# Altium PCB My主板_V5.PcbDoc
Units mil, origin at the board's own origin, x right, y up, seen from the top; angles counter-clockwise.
Board outline 4125 x 2480.2 mil, 2 copper layers (Top Layer, Bottom Layer); 56 components, 56 nets, 301 pads, 42 vias.
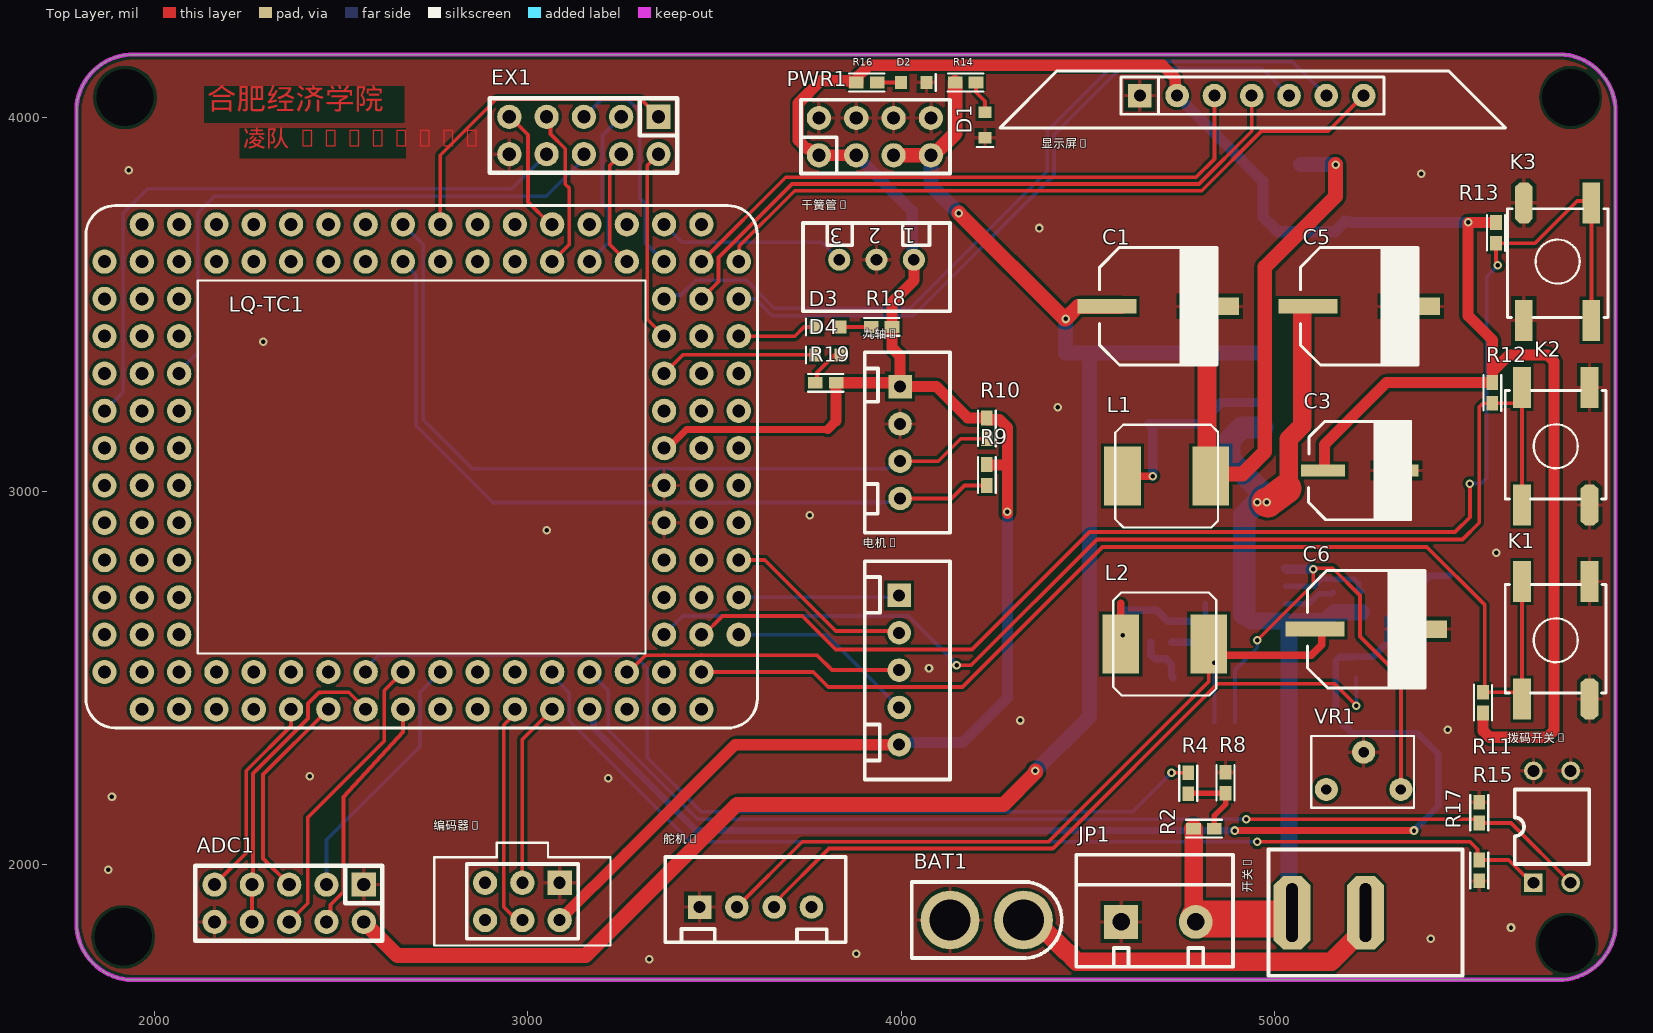
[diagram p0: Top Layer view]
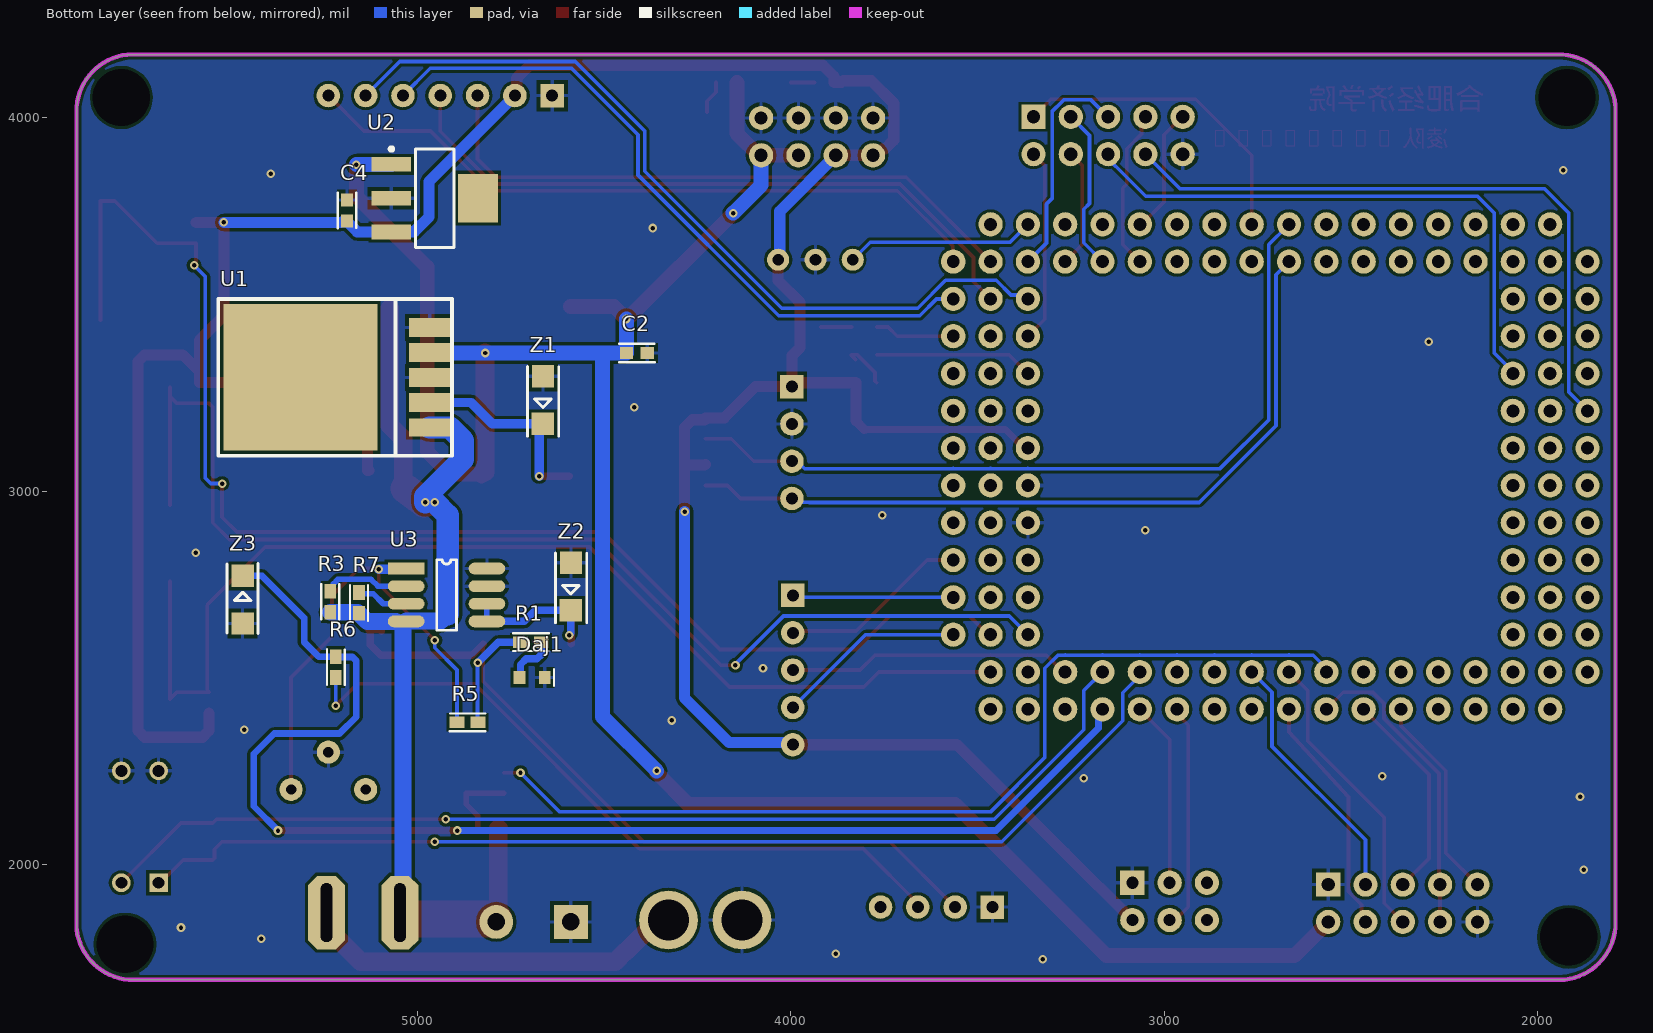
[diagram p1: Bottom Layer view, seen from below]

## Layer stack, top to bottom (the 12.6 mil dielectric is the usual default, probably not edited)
Top Solder: solder mask 0.4, Solder Resist, Dk 3.5
Top Layer: signal copper 1.4
Dielectric 1: dielectric 12.6, FR-4, Dk 4.8
Bottom Layer: signal copper 1.4
Bottom Solder: solder mask 0.4, Solder Resist, Dk 3.5

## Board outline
1790,1830 ccw(c1943.01,1842.73) 1925.4,1690.2 1925.4,1689.8 5775,1689.8 5775,1690 ccw(c5762.27,1843.01) 5914.8,1825.4 5915,1825.4 5915,4030 ccw(c5761.99,4017.27) 5779.6,4169.8 5779.6,4170 1930,4170 ccw(c1942.73,4016.99) 1790.2,4034.6 1790,4034.6

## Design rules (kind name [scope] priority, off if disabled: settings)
Clearance [All] p1: gap=8 ignorepadtopadclearanceinfootprint=FALSE
PolygonConnect [All] p1: thpad.connectstyle=Relief thpad.reliefconductorwidth=10 thpad.reliefentries=4 thpad.polygonreliefangle="90 Angle" thpad.airgapwidth=10 smdpad.connectstyle=Relief smdpad.reliefconductorwidth=10 smdpad.reliefentries=4 smdpad.polygonreliefangle="90 Angle" smdpad.airgapwidth=10 via.connectstyle=Direct via.reliefconductorwidth=10 via.reliefentries=4 via.polygonreliefangle="90 Angle" via.airgapwidth=10
RoutingVias [All] p1: holewidth=12 width=25 viastyle="Through Hole" minholewidth=12 minwidth=22 maxholewidth=12 maxwidth=50
SolderMaskExpansion [All] p1: expansion=4 istentingtop=FALSE
Width 12V [InNetClass('12V')] p1: maxlimit=100 minlimit=10 preferedwidth=50
Width 5V [InNetClass('5V')] p2: maxlimit=100 minlimit=10 preferedwidth=40
Width 3.3V [InNetClass('3.3V')] p3: maxlimit=100 minlimit=10 preferedwidth=30
Width [All] p4: maxlimit=100 minlimit=10 preferedwidth=10
30 further rules are at their usual default settings.

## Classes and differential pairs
net class 3.3V: 3.3V
net class 5V: 5V
net class 12V: BAT12V VCC12V

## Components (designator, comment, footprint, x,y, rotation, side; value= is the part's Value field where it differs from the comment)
ADC1 "双排针2*5 2.5mm" LQ_IDC5X2 2560,1945 r180 top
BAT1 "XT30UPB-M公头" LQ_XT30UPB-F 4230,1850 r180 top
C1 "470uf/16V  8*10" LQ_C8X10 4690,3495 r180 top
C2 "104nF" LQ_C0603 4441,3370 r180 bottom value=104
C3 "470uf/10V  6.3*7.7" LQ_C6d3X7d7 5230,3055 r180 top
C4 "104nF" LQ_C0603 5190,3780 r270 bottom value=104
C5 "220uf/16V  8*10" LQ_C8X10 5228.43,3495 r180 top
C6 "470uf/16V  8*10" LQ_C8X10 5247.2,2630 r180 top
D1 "LED红" LQ_LED0603R 4225,4015 r270 top
D2 "LED红" LQ_LED0603R 4000,4095 r0 top
D3 "LED红" LQ_LED0603R 3838,3440 r180 top
D4 "LED红" LQ_LED0603R 3838,3365 r180 top
Daj1 "LED红" LQ_LED0603R 4728,2500 r180 bottom
EX1 "单排针2*5-2.54mm" LQ_IDC5X2 3350,4003 r180 top
JP1 "HDR-1X2" KF301-5.0-2P 4790,1845 r0 top
K1 "微动开关6*6*6" LQ_BT4SMT 5755,2600 r180 top
K2 "微动开关6*6*6" LQ_BT4SMT 5755,3120 r180 top
K3 "微动开关6*6*6" LQ_BT4SMT 5760,3615 r0 top
L1 "33uH" LQ_L7X7 4593.78,3040 r0 top
L2 "33uH" LQ_L7X7 4588.78,2590 r0 top
LQ-TC1 "LQ-TC264-SYSVC" LQ-TC264-SYSVC-S 1965,2415 r0 top
PWR1 "双排针4X2-2.54" LQ_IDC4X2 3780,3900 r90 top
R1 "3K3" LQ_R0603 4669,2595 r0 bottom
R2 "4.7K" LQ_R0603 4784,2095 r0 top
R3 "1K" LQ_R0603 5235,2731 r270 bottom
R4 "2K" LQ_R0603 4770,2245 r270 top
R5 "1K" LQ_R0603 4895,2380 r180 bottom
R6 "2K" LQ_R0603 5220,2556 r270 bottom
R7 "2.7K" LQ_R0603 5158,2672 r90 bottom
R8 "1K" LQ_R0603 4870,2190 r90 top
R9 "2.2K" LQ_R0603 4230,3071 r270 top
R10 "2.2K" LQ_R0603 4230,3140 r90 top
R11 "1K" LQ_R0603 5560,2461 r270 top
R12 "1K" LQ_R0603 5585,3235 r90 top
R13 "1K" LQ_R0603 5595,3664 r90 top
R14 "1K" LQ_R0603 4145,4095 r0 top
R15 "2.2K" LQ_R0603 5550,2110 r90 top
R16 "1K" LQ_R0603 3880,4095 r0 top
R17 "2.2K" LQ_R0603 5550,2011 r270 top
R18 "1K" LQ_R0603 3976,3440 r180 top
R19 "1K" LQ_R0603 3826,3290 r180 top
U1 "LM2596CS-5.0V" LQ_TO-263-5 4968.54,3170.35 r90 bottom
U2 "LM39100 3.3V" SOT223_M 4955,3785 r180 bottom
U3 "AS1015" SOP8 5031.54,2792.24 r180 bottom
VR1 "2k" lq_3266 5140,2200 r0 top
Z1 "1N5824" LQ_1206D 4664.61,3307.56 r270 bottom
Z2 "1N5824" LQ_1206D 4589.61,2807.56 r270 bottom
Z3 "ZMM3V3" LQ_1206D 5470,2645 r90 bottom
九轴1 "插针1*4" LQ_XH254-4P 4017.05,3280 r270 top
干簧管1 "XH254-3P" LQ_XH254-3P 4034.37,3620 r180 top
开关1 "KCD1-101 117S" "LQ_KCD1-101 117S" 5245,1870 r0 top
拨码开关1 "SW-DIP2" DIP4 5695,1950 r90 top
显示屏1 "单排座1*7-2.54" LQ-TFT-180V33 4940,4060 r0 top
电机1 "XH254-4P" LQ_XH254-5P 3995,2520 r270 top
编码器1 "双排针2*3 2.54mm" LQ_ENCODER 3085,1950 r180 top
舵机1 "插针1*4-2.54" LQ_XH254-4P 3460,1904.68 r0 top

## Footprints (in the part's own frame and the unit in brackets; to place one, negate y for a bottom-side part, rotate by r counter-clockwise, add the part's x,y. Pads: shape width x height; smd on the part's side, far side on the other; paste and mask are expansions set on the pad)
DIP4 [mil]
  rect 50x50 hole 32: 1(0,0)
  round 50 hole 32: 2(0,-100) 3(300,-100) 4(300,0)
  silkscreen extent 50,-150 250,50, body extent -45,-170 345,70, height 276
KF301-5.0-2P [mm]
  rect 2.3x2.3 hole 1.2: 1(-5.08,0)
  round 2.3 hole 1.2: 2(0,0)
  silkscreen extent -8.13,-3.05 2.54,4.57, body extent -7.95,-3 2.55,4.6, height 10.05
LQ-TC264-SYSVC-S [mm] "单片机核心板封装库"
  round 1.65 hole 0.88: 1(5.08,0) 2(5.08,2.54) 3(7.62,0) 4(7.62,2.54) 5(10.16,0) 6(10.16,2.54) 7(12.7,0) 8(12.7,2.54) 9(15.24,0) 10(15.24,2.54) 11(17.78,0) 12(17.78,2.54) 13(20.32,0) 14(20.32,2.54) 15(22.86,0) 16(22.86,2.54) 17(25.4,0) 18(25.4,2.54) 19(27.94,0) 20(27.94,2.54) 21(30.48,0) 22(30.48,2.54) 23(33.02,0) 24(33.02,2.54) 25(35.56,0) 26(35.56,2.54) 27(38.1,0) 28(38.1,2.54) 30(38.1,5.08) 31(35.56,5.08) 33(38.1,7.62) 34(35.56,7.62) 36(38.1,10.16) 37(35.56,10.16) 39(38.1,12.7) 40(35.56,12.7) 42(38.1,15.24) 43(35.56,15.24) 45(38.1,17.78) 46(35.56,17.78) 48(38.1,20.32) 49(35.56,20.32) 51(38.1,22.86) 52(35.56,22.86) 54(38.1,25.4) 55(35.56,25.4) 57(38.1,27.94) 58(35.56,27.94) 60(38.1,30.48) 61(35.56,30.48) 62(38.1,33.02) 63(35.56,33.02) 64(33.02,33.02) 65(33.02,30.48) 66(30.48,33.02) 67(30.48,30.48) 68(27.94,33.02) 69(27.94,30.48) 70(25.4,33.02) 71(25.4,30.48) 72(22.86,33.02) 73(22.86,30.48) 74(20.32,33.02) 75(20.32,30.48) 76(17.78,33.02) 77(17.78,30.48) 78(15.24,33.02) 79(15.24,30.48) 80(12.7,33.02) 81(12.7,30.48) 82(10.16,33.02) 83(10.16,30.48) 84(7.62,33.02) 85(7.62,30.48) 86(5.08,33.02) 87(5.08,30.48) 88(2.54,33.02) 89(0,33.02) 90(2.54,30.48) 91(0,30.48) 93(2.54,27.94) 94(0,27.94) 96(2.54,25.4) 97(0,25.4) 99(2.54,22.86) 100(0,22.86) 102(2.54,20.32) 103(0,20.32) 105(2.54,17.78) 106(0,17.78) 108(2.54,15.24) 109(0,15.24) 111(2.54,12.7) 112(0,12.7) 114(2.54,10.16) 115(0,10.16) 117(2.54,7.62) 118(0,7.62) 120(2.54,5.08) 121(0,5.08) 123(2.54,2.54) 124(0,2.54) 126(2.54,0) 127(0,0)
  round 1.65 hole 0.88 mask+0.102: 29(40.64,5.08) 32(40.64,7.62) 35(40.64,10.16) 38(40.64,12.7) 41(40.64,15.24) 44(40.64,17.78) 47(40.64,20.32) 50(40.64,22.86) 53(40.64,25.4) 56(40.64,27.94) 59(40.64,30.48) 92(-2.54,30.48) 95(-2.54,27.94) 98(-2.54,25.4) 101(-2.54,22.86) 104(-2.54,20.32) 107(-2.54,17.78) 110(-2.54,15.24) 113(-2.54,12.7) 116(-2.54,10.16) 119(-2.54,7.62) 122(-2.54,5.08) 125(-2.54,2.54)
  silkscreen extent -3.81,-1.27 41.91,34.29
LQ-TFT-180V33 [mm]
  rect 1.6x1.6 hole 0.82: 1(-7.62,0)
  round 1.6 hole 0.82: 2(-5.08,0) 3(-2.54,0) 4(0,0) 5(2.54,0) 6(5.08,0) 7(7.62,0)
  silkscreen extent -17.13,-2.19 17.27,1.69
LQ_1206D [mil]
  rect 60x60 smd: 1(0,0) 2(127.56,-0.39)
  silkscreen extent -27,-41 161,42, body extent -4,-30 133,29, height 61
lq_3266 [mil]
  round 62 hole 28: 1(0,0) 2(100,100) 3(200,0)
  silkscreen extent -40,-49 235,143
LQ_BT4SMT [mm]
  oct 1.2x2.8 smd: 1(-2.3,4)
  rect 1.2x2.8 smd: 1(-2.3,-4) 2(2.3,4) 2(2.3,-4)
  silkscreen extent -3.42,-3.8 3.44,3.6, body extent -3,-5.08 3,4.92, height 4.54
LQ_C6d3X7d7 [mm]
  rect 3x0.8 smd: 1(2.5,0) 2(-2.5,0)
  silkscreen extent -3.49,-3.37 3.49,3.35, body extent -3.5,-3.3 3.5,3.3, height 7.7
LQ_C8X10 [mm]
  rect 4x1 smd: 1(3.5,0)
  rect 4x1.2 smd: 2(-3.5,0)
  silkscreen extent -4,-4 4,4, body extent -4.95,-4.15 4.95,4.15, height 10.2
LQ_C0603 [mm]
  rect 0.9x0.8 smd: 1(0,0) 2(1.422,0)
  silkscreen extent -0.5,-0.64 1.92,0.64, body extent -0.08,-0.4 1.52,0.4, height 0.3
LQ_ENCODER [mm]
  rect 1.65x1.65 hole 0.82: 1(0,0)
  round 1.65 hole 0.82: 2(0,2.54) 3(2.54,0) 4(2.54,2.54) 5(5.08,0) 6(5.08,2.54)
  silkscreen extent -3.46,-2.73 8.54,4.27, body extent -1.31,-1.31 6.31,3.77, height 8.5
LQ_IDC4X2 [mm]
  round 1.65 hole 0.9: 1(0,0) 2(2.54,0) 3(0,-2.54) 4(2.54,-2.54) 5(0,-5.08) 6(2.54,-5.08) 7(0,-7.62) 8(2.54,-7.62)
  silkscreen extent -1.24,-8.92 3.78,1.22, body extent -1.17,-9.01 3.83,1.4, height 8.5
LQ_IDC5X2 [mm]
  rect 1.65x1.65 hole 0.9: 1(0,0)
  round 1.65 hole 0.9: 2(0,2.54) 3(2.54,0) 4(2.54,2.54) 5(5.08,0) 6(5.08,2.54) 7(7.62,0) 8(7.62,2.54) 9(10.16,0) 10(10.16,2.54)
  silkscreen extent -1.27,-1.27 11.48,3.81, body extent -1.25,-1.26 11.45,3.82, height 8.5
"LQ_KCD1-101 117S" [mm]
  oct 2.5x5 hole 0.8 slot 4 at 90 deg: 1(0,0) 2(-5,0)
  silkscreen extent -6.61,-4.3 6.6,4.3
LQ_L7X7 [mm]
  rect 2.5x4 smd: 1(0,0) 2(6,0)
  silkscreen extent -0.5,-3.5 6.5,3.5
LQ_LED0603R [mm]
  rect 0.8x0.9 smd: 1(0,0) 2(1.727,0)
  silkscreen extent 2.36,-0.56 2.36,0.58, body extent 0.02,-0.45 1.72,0.45, height 0.9
LQ_R0603 [mm]
  rect 1x0.8 smd: 1(0,0) 2(1.422,0)
  silkscreen extent -0.5,-0.61 1.92,0.61, body extent -0.08,-0.4 1.52,0.4, height 0.48
LQ_TO-263-5 [mil]
  rect 393.7x413.39 smd: 0(134.65,346.46)
  rect 48x110 smd: 1(0,0)
  rect 50x110 smd: 2(67,0) 3(134,0) 4(201,0) 5(268,0)
  silkscreen extent -76,-60 344,567, body extent -65,-16 335,536, height 180
LQ_XH254-3P [mm]
  round 1.5 hole 0.8: 1(0,0) 2(2.54,0) 3(5.08,0)
  silkscreen extent -2.46,-2.5 7.54,3.5, body extent -2.43,-2.37 7.57,3.33, height 7
LQ_XH254-4P [mm]
  rect 1.6x1.6 hole 0.82: 1(0,-0.5)
  round 1.6 hole 0.82: 2(2.54,-0.5) 3(5.08,-0.5) 4(7.62,-0.5)
  silkscreen extent -2.33,-2.9 9.96,2.9, body extent -2.45,-2.81 10.05,2.89, height 7
LQ_XH254-5P [mm]
  rect 1.6x1.6 hole 0.82: 1(-5.08,0)
  round 1.6 hole 0.82: 2(-2.54,0) 3(0,0) 4(2.54,0) 5(5.08,0)
  silkscreen extent -7.42,-2.34 7.45,3.46, body extent -7.52,-2.31 7.48,3.39, height 7
LQ_XT30UPB-F [mm]
  round 4 hole 2.8: 1(2.5,0) 2(-2.5,0)
  silkscreen extent -5.1,-2.59 5.11,2.6
SOP8 [mm]
  rect 2.5x0.8 smd: 1(0,0)
  oval 2.5x0.8 smd: 2(0,-1.2) 3(0,-2.4) 4(0,-3.6) 5(5.5,-3.6) 6(5.5,-2.4) 7(5.5,-1.2) 8(5.5,0)
  silkscreen extent 2.08,-4.2 3.41,0.6
SOT223_M [mm] "SOT223, 4-Leads, Body 6.5x3.5mm, Pitch 2.3mm, Lead Span 7mm, IPC Low Density"
  rect 2.7x1 smd: 1(-2.95,2.3) 2(-2.95,0) 3(-2.95,-2.3)
  rect 2.7x3.3 smd: 4(2.95,0)
  silkscreen extent -3.08,-3.35 1.3,3.47, body extent -1.85,-3.35 1.85,3.35, height 1.7

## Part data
ADC1: library part CON10, "Connector"
BAT1: library part LQ_PIN2, "Jumper"
C1 C3 C5 C6: library part "CAPACITOR POL", "Capacitor"
C2 C4: library part Cap, "Capacitor"
D1 D2 D3 D4: library part LED
Daj1: library part LQ_LED
EX1: library part "HEADER 5X2"
JP1: library part "Header 2_1", "2P接插件"
K1 K2 K3: library part 微动开关
L1 L2: library part INDUCTOR
PWR1: library part "HEADER 4X2"
R1 R2 R3 R4 R5 R6 R7 R8 R9 R10 R11 R12 R13 R14 R15 R16 R17 R18 R19: library part RES2
U1: library part LM2575T
U2: library part VOLTREG
VR1: library part "RESISTOR TAPPED"
Z1 Z2 Z3: library part LQ_D, "Schottky Diode"
九轴1 舵机1: library part CON4, "Connector"
干簧管1: library part "HEADER 3"
开关1: library part LQ_SWMTS102, "LQ_SWMTS102"
显示屏1: library part LQ_OLED128X64
电机1: library part "Header 5", "Header, 5-Pin"
编码器1: library part "Header 3X2", "Header, 3-Pin, Dual row"

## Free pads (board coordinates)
  round 60 hole 153.54: 2(1915,1805) 2(1920,4055) 2(5785,1785) 2(5795,4055)

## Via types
v1: diameter 23, hole 12, Top Layer to Bottom Layer, tented both sides, 42 vias

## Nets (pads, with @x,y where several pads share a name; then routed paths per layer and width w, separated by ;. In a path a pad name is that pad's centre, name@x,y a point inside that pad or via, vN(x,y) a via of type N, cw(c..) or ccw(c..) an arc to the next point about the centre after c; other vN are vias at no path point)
3.3V: C3.1 C4.2 LQ-TC1.46 PWR1.1 PWR1.3 R9.1 R10.2 R11.2 R12.2 R13.2 R16.1 R18.1 R19.1 U2.3 九轴1.1 干簧管1.1 显示屏1.2 电机1.5 编码器1.2 | length 8951
  Top Layer w18: LQ-TC1.46 3375,3115 3425,3165 3803.43,3165
  Top Layer w25: 3803.43,3165 3826,3187.57
  Top Layer w30: 编码器1.2 3265,2030 3555,2320 电机1.5 ; PWR1.1 3770.54,3900 3753.25,3917.29 3747.71,3917.29 3724.52,3940.48 3724.52,4039.52 3785,4100 3860.78,4100 3865.03,4095.75 3875.32,4095.75 3876.06,4095 3883.94,4095 3884.68,4095.75 3884.68,4105 3884.68,4111.65 3914.13,4141.09 4701.33,4141.09 4735,4107.43 4735,4065 显示屏1.2 ; PWR1.1@3801.54,3900 PWR1.3 ; 3826,3187.57 R19.1 3987.36,3290 九轴1.1 3997.36,3362.64 3976,3384 R18.1 3976,3506 4034.37,3564.37 干簧管1.1 ; 九轴1.1@4020,3280 4095,3280 4179,3196 R10.2 4230,3192.06 4230.75,3191.32 4263.69,3191.32 4285,3170 v1(4285,2945) v1@4285,2940.07 ; R9.1 4230,3070.75 4230.75,3070 4270.07,3070 ; C3.1 5134.25,3055 5135,3055.75 5135,3125 5301,3291 R12.2 5585.75,3291.75 5585.75,3320.75 5630,3365 5732.43,3365 5750,3347.43 5750,2357.57 5732.43,2340 5577.57,2340 5560,2357.57 R11.2 ; 5585,3320.75 5585,3405 5520,3470 v1(5520,3720) R13.2
  Bottom Layer w30: PWR1.3 4030,3750 4030,3624.37 干簧管1.1 ; 电机1.5 4001.31,2326.31 4166.31,2326.31 4285,2445 v1(4285,2945) ; 显示屏1.2 4970,3830 4970,3735 5010,3695 5070.59,3695 U2.3 5162.42,3694.45 C4.2@5190,3722.03 ; C4.2 C4.2@5190,3722.03 ; v1(5520,3720) 5206.25,3720 5204.97,3721.28 5190.75,3721.28 C4.2@5190,3722.03
5V: ADC1.2 C1.1 C2.1 L1.2 PWR1.5 PWR1.7 R14.1 U1.4 U2.1 | length 6373.3
  Top Layer w40: ADC1.2 2650,1755 3155,1755 3560,2160 4275,2160 4360,2245 v1(4360,2250) ; PWR1.5 PWR1.7 4086.75,3900 4145,3958.25 R14.1 ; v1(4155,3745) 4438.8,3461.2 v1(4441,3461.2) 4474.8,3495 C1.1@4591.57,3495 ; L1.2@4820,3050 L1.2 4836.12,3046.12 4915.78,3046.12 4975,3105.34 4975,3600 5165,3790 v1(5165,3875)
  Top Layer w50: L1.2@4820,3050 v1(4820,3370)
  Bottom Layer w40: PWR1.7 4080,3820 v1(4155,3745) ; v1(4360,2250) 4505,2395 4505,3370 ; v1(4441,3461.2) C2.1 4505,3370 ; U1.4 4967.19,3370 v1(4820,3370) 4505,3370 ; U2.1 5164.45,3875.55 v1(5165,3875)
13.0: EX1.1 LQ-TC1.74 | length 851.6
  Top Layer w10: LQ-TC1.74 2765,3900 2915,4050 3303,4050 EX1.1
AN1: ADC1.3 LQ-TC1.14 | length 696.3
  Bottom Layer w10: ADC1.3 2460,2065 2710.48,2315.48 2710.48,2460.48 LQ-TC1.14
AN2: ADC1.4 LQ-TC1.11 | length 650.8
  Top Layer w10: ADC1.4 2470.52,1855.52 2470.52,1891.2 2505.48,1926.16 2505.48,2180.06 2665,2354.34 LQ-TC1.11
AN3: ADC1.5 LQ-TC1.7 | length 571.5
  Top Layer w10: ADC1.5 2290,2015 2290,2240 LQ-TC1.7
AN4: ADC1.6 LQ-TC1.12 | length 796.3
  Top Layer w10: ADC1.6 2410,1895 2410,2125 2615,2330 2615,2465 LQ-TC1.12
AN5: ADC1.7 ADC1.8 LQ-TC1.9 | length 833.6
  Top Layer w10: ADC1.8 ADC1.7 2263,1948 2263,2242.54 2410.48,2390.02 2410.48,2430.48 2440,2460 2445.68,2460 2446.16,2460.48 2519.52,2460.48 LQ-TC1.9
AN6: ADC1.9 LQ-TC1.5 | length 554.9
  Top Layer w10: ADC1.9 2245,2030 2245,2250 2365,2370 LQ-TC1.5
AN7: LQ-TC1.10 R4.1 | length 2587.5
  Top Layer w10: v1(4725,2245) R4.1
  Bottom Layer w10: LQ-TC1.10 2565,2525 2600,2560 2658.41,2560 cw(c2665,2515) 2671.59,2560 2758.41,2560 cw(c2765,2515) 2771.59,2560 2858.41,2560 cw(c2865,2515) 2871.59,2560 2958.41,2560 cw(c2965,2515) 2971.59,2560 3058.41,2560 cw(c3065,2515) 3071.59,2560 3158.41,2560 cw(c3165,2515) 3171.59,2560 3258.41,2560 cw(c3265,2515) 3271.59,2560 3284.32,2560 3319.52,2524.8 3319.52,2285.48 3465,2140 4620,2140 v1(4725,2245)
BAT12V: C5.1 JP1.2 R2.1 R3.2 R7.1 U1.1 U3.4 开关1.2 | length 2795.2
  Top Layer w50: R2.1 4785,2094 4785,1850 JP1.2 ; 开关1.2@5030.91,1852.76 开关1.2 ; 5033.94,3007.12 5039.52,3012.7 5039.52,3139.52 5075,3175 C5.1@5075,3489.69
  Top Layer w80: v1(4980,2970) 4983.47,2969.49 5033.94,3007.12
  Top Layer w100: JP1.2@4797.76,1852.76 开关1.2@5030.91,1852.76
  Bottom Layer w45: 4920,2670 4938.49,2651.51 5030.54,2651.51 U3.4 5033.09,2650.51 5039.84,2643.76 5039.84,1886.05 开关1.2@5035.97,1882.18 ; U3.4@5058.25,2650 5136,2650 R7.1 ; R7.1@5161,2675 R3.2
  Bottom Layer w60: 4920,2670 4920,2935 v1(4955,2970) ; U1.1 4914.47,3170.35 4879.32,3135.21 4879.32,3085.5 4980,2984.83 v1(4980,2970) ; 开关1.2@5035.97,1882.18 开关1.2
"Dial SW0": LQ-TC1.20 R17.1 拨码开关1.1 | length 2927.9
  Top Layer w10: v1(4955,2060) 5525,2060 5545.17,2039.83 5545.17,2015.83 R17.1 5629,2011 5670,1970 5675,1970 拨码开关1.1
  Bottom Layer w10: LQ-TC1.20 3065,2505 3110.48,2459.52 3110.48,2384.52 3435,2060 v1(4955,2060)
"Dial SW1": LQ-TC1.22 R15.1 拨码开关1.2 | length 2925.5
  Top Layer w10: v1(4925,2120) 5540,2120 R15.1 5575,2110 5635,2110 拨码开关1.2
  Bottom Layer w10: LQ-TC1.22 3215,2465 3215,2360 3455,2120 v1(4925,2120)
ENcoder1A: LQ-TC1.19 编码器1.3 | length 498.1
  Top Layer w10: 编码器1.3 2985,2334.54 3065,2414.54 LQ-TC1.19
ENcoder1B: LQ-TC1.17 编码器1.4 | length 606.7
  Top Layer w10: LQ-TC1.17 2965,2402.5 2935,2372.5 2935,1885.38 2970.38,1850 编码器1.4
GND: ADC1.1 ADC1.10 BAT1.1 C1.2 C2.2 C3.2 C4.1 C5.2 C6.2 D1.2 D2.2 Daj1.2 EX1.10 JP1.1 K1.1 K2.1 K3.1 LQ-TC1.40 LQ-TC1.43 PWR1.2 PWR1.4 PWR1.6 PWR1.8 R8.2 R15.2 R17.2 U1.3 U1.5 U2.2 U3.7 U3.8 VR1.2 Z1.1 Z2.1 Z3.1 九轴1.2 干簧管1.2 拨码开关1.3 拨码开关1.4 显示屏1.1 编码器1.1 舵机1.1
  other v1: 3325,1745 3880,1760 5420,1800 5635,1830 1875,1985 1885,2180 3215,2230 2415,2235 5465,2360 4320,2385 4075,2525 5595,2835 3050,2895 3755,2935 4420,3225 2290,3400 4370,3705 5395,3850 1930,3860
KEY0: K1.2 LQ-TC1.28 R11.1 | length 2998.7
  Top Layer w10: LQ-TC1.28 3765,2515 3805,2475 4165,2475 4540,2850 5409.14,2850 5565,2694.14 5565,2466 R11.1 5565,2461 5645.97,2461 5664.45,2442.52 K1.2@5664.45,2757.48
KEY1: K2.2 LQ-TC1.31 R12.1 | length 3171.9
  Top Layer w10: v1(4148.79,2532.93) 4187.93,2532.93 4525,2870 5505,2870 5550,2915 5550,3225 5560,3235 R12.1 5645.83,3235 K2.2@5664.45,3253.62 ; K2.2@5664.45,2962.52 K2.2@5664.45,3253.62 ; K2.2@5664.45,3277.48 K2.2@5664.45,3253.62
  Bottom Layer w10: LQ-TC1.31 3415,2665 4020,2665 4148.79,2536.21 v1(4148.79,2532.93)
KEY2: K3.2 LQ-TC1.30 R13.1 | length 3672.1
  Top Layer w10: LQ-TC1.30 3471.2,2615 3521.2,2665 3735,2665 3825,2575 4190,2575 4505,2890 5485,2890 5525,2930 v1(5525,3020) ; v1(5600,3605) 5600,3608.52 5595,3613.52 R13.1 5699,3664 5812.38,3777.38 5850.55,3777.38 5850.55,3772.48 K3.2@5850.55,3457.52
  Bottom Layer w10: v1(5525,3020) 5555,3020 5570,3035 5570,3575 v1(5600,3605)
MB_LED0: D4.2 LQ-TC1.52 | length 425.7
  Top Layer w10: LQ-TC1.52 3415,3365 D4.2
MB_LED1: D3.2 LQ-TC1.53 | length 215.4
  Top Layer w10: LQ-TC1.53 3715,3415 3740,3440 D3.2
"MT1 N": LQ-TC1.24 电机1.3 | length 765.3
  Top Layer w10: LQ-TC1.24 3270,2515 3315,2560 3358.41,2560 cw(c3365,2515) 3371.59,2560 3458.41,2560 cw(c3465,2515) 3471.59,2560 3775,2560 3815,2520 电机1.3
MT1_P: LQ-TC1.29 电机1.4 | length 510.8
  Bottom Layer w10: LQ-TC1.29 3800,2615 电机1.4
MT2_N: LQ-TC1.32 电机1.1 | length 432.1
  Bottom Layer w10: LQ-TC1.32 3990,2715 电机1.1
MT2_P: LQ-TC1.35 电机1.2 | length 510.8
  Top Layer w10: LQ-TC1.35 3635,2815 3824.95,2625.05 3989.95,2625.05 电机1.2
NetC6_1: C6.1 L2.2 R1.2 R5.2 舵机1.2 | length 2320.8
  Top Layer w10: 舵机1.2 3735,2060 4395.23,2060 4825,2489.77 L2.2
  Top Layer w20: L2.2 4855,2560 5100,2560 5127.73,2587.73 5127.73,2626.15 5131.57,2630 5103.29,2630 C6.1@5097.54,2624.25
  Bottom Layer w10: R5.2 4840,2381 v1(4840,2540)
  Bottom Layer w20: R1.2 4785,2595 v1(4840,2540)
NetD1_1: D1.1 R14.2 | length 89.9
  Top Layer w10: R14.2 4201,4069 4225,4045 D1.1
NetD2_1: D2.1 R16.2 | length 64
  Top Layer w10: R16.2 D2.1
NetD3_1: D3.1 R18.2 | length 82
  Top Layer w10: D3.1 R18.2
NetD4_1: D4.1 R19.2 | length 129.8
  Top Layer w10: R19.2 3774.89,3294.89 3774.89,3318.04 3821.85,3365 D4.1 3838,3363.03 D4.1@3827.25,3352.28
NetDaj1_1: Daj1.1 R1.1 | length 136.6
  Bottom Layer w20: R1.1 4669,2561.72 4680.72,2550 4710,2550 4725,2535 4725,2503 Daj1.1
NetL1_1: L1.1 U1.2 Z1.2 | length 552.7
  Top Layer w20: L1.1 v1(4675,3040)
  Bottom Layer w25: v1(4675,3040) 4675,3170 Z1.2 4800,3180 4857.35,3237.35 U1.2
NetL2_1: L2.1 U3.5 U3.6 Z2.2 | length 461
  Top Layer w20: L2.1 4588.78,2698.78
  Bottom Layer w15: U3.5 U3.6
  Bottom Layer w20: v1(4593.78,2613.78) 4593.78,2614.59 4590,2618.37 Z2.2 4685,2680 4714.49,2650.51 U3.5
NetR2_2: R2.2 R4.2 R8.1 | length 207.4
  Top Layer w15: R4.2@4770,2190 R8.1 4870,2160 4840,2130 R2.2
NetR3_1: R3.1 U3.2 | length 231.3
  Bottom Layer w15: U3.2 5107.47,2745 5125.66,2763.18 5214.78,2763.18 5226.75,2751.21 5226.75,2739.25 R3.1
NetR5_1: R5.1 U3.1 VR1.3 | length 1298
  Top Layer w10: v1(4955,2600) 5105,2750 v1(5105,2790) 5107.49,2792.49 5116.68,2792.49 5117.19,2793 5157,2793 5230,2720 5230,2610 5340,2500 VR1.3
  Bottom Layer w10: R5.1 4895,2520 4955,2580 v1(4955,2600) ; U3.1 U3.1@5034.79,2795.5
  Bottom Layer w25: U3.1 5033.78,2790 v1(5105,2790)
NetR6_2: R6.2 舵机1.3 | length 1913.2
  Top Layer w10: 舵机1.3 3660,1895 3807,2042 4407,2042 4848.76,2483.76 5161.24,2483.76 v1(5220,2425)
  Bottom Layer w10: v1(5220,2425) R6.2
NetR7_2: R7.2 U3.3 | length 139
  Bottom Layer w15: U3.3 5092.76,2697.76 5120,2725 5155,2725 R7.2
P15.2: EX1.3 LQ-TC1.67 | length 435.8
  Bottom Layer w10: LQ-TC1.67 3215.26,3665.26 3215.26,3755.26 3200,3770.52 3200,3953 EX1.3
P15.5: EX1.5 LQ-TC1.61 | length 611
  Bottom Layer w10: EX1.5 3195.48,4048.48 3231.16,4048.48 3268.84,4048.48 3273.66,4043.66 3300,4017.32 3300,3784.04 3315,3769.04 3315,3665 LQ-TC1.61
P15.7: EX1.7 LQ-TC1.69 | length 431.9
  Top Layer w10: EX1.7 3060.52,3992.48 3060.52,3956.8 3100,3917.32 3100,3822.38 3110.48,3811.9 3110.48,3660.48 LQ-TC1.69
P15.8: EX1.9 LQ-TC1.68 | length 339.7
  Top Layer w10: EX1.9 2952,4003 3000,3955 3000,3775 3060,3715 LQ-TC1.68
Reed: LQ-TC1.63 干簧管1.3 | length 508.7
  Bottom Layer w10: LQ-TC1.63 3413.07,3666.93 3787.44,3666.93 干簧管1.3
RX1: EX1.2 LQ-TC1.55 | length 519.5
  Top Layer w10: EX1.2 3319.52,3872.52 3319.52,3460.48 LQ-TC1.55
RX3: EX1.6 LQ-TC1.99 | length 1558.3
  Bottom Layer w10: LQ-TC1.99 2065,3320 2115,3370 2115,3745 2160,3790 3049.14,3790 3104.14,3845 3150,3890.86 EX1.6
SCL: LQ-TC1.77 R9.2 九轴1.4 | length 2065.8
  Top Layer w10: 九轴1.4@4020,2980 4135,2980 4170,3015 R9.2
  Bottom Layer w10: LQ-TC1.77 2700,3580 2700,3175 2905.48,2969.52 3950.48,2969.52 3950.87,2969.91 3987.27,2969.91 九轴1.4
SDA: LQ-TC1.76 R10.1 九轴1.3 | length 2125.2
  Top Layer w10: 九轴1.3@4020,3080 4100,3080 4160,3140 R10.1
  Bottom Layer w10: LQ-TC1.76 2665,3710 2670,3710 2719.52,3660.48 2719.52,3190.48 2847.07,3062.93 2850,3060 3358.41,3060 cw(c3365,3015) 3371.59,3060 3458.41,3060 cw(c3465,3015) 3471.59,3060 3558.41,3060 cw(c3565,3015) 3571.59,3060 3963.02,3060 3983.02,3080 九轴1.3
SErvo_P1: LQ-TC1.21 R6.1 Z3.2 | length 3503
  Top Layer w18: v1(4895,2090) v1(5375,2090)
  Bottom Layer w18: LQ-TC1.21 3175.52,2404.48 3175.52,2364.48 3450,2090 v1(4895,2090) ; v1(5375,2090) 5440,2155 5440,2295 5385,2350 5210,2350 5165,2395 5165,2544.46 5175.54,2555 5213.25,2555 5214.25,2556 5266,2556 5305,2595 5305,2660 5417.56,2772.56 Z3.2
TFT_CS: LQ-TC1.59 显示屏1.7 | length 1882.8
  Top Layer w10: LQ-TC1.59 3566.62,3616.62 3566.62,3656.62 3715,3805 4805.91,3805 4965.91,3965 5145,3965 显示屏1.7
TFT_DC: LQ-TC1.58 显示屏1.6 | length 2206.6
  Bottom Layer w10: LQ-TC1.58 3375.52,3525.52 3410.52,3525.52 3450,3565 3585.46,3565 3660.46,3490 4025,3490 4392,3857 4392,3965 4578.09,4151.09 5048.91,4151.09 显示屏1.6 显示屏1.6@5140,4055
TFT_RST: LQ-TC1.56 显示屏1.5 | length 1861.8
  Bottom Layer w10: LQ-TC1.56 3610,3515 3655,3470 4033,3470 4410,3847 4410,3955 4588.09,4133.09 4966.91,4133.09 显示屏1.5
TFT_SCK: LQ-TC1.57 显示屏1.4 | length 1795
  Top Layer w10: LQ-TC1.57 3510.84,3560.84 3510.84,3626.29 3707.54,3823 3735,3823 4798.46,3823 4940,3964.54 显示屏1.4
TFT_SDI: LQ-TC1.60 显示屏1.3 | length 1658.9
  Top Layer w10: LQ-TC1.60 3691,3841 4791,3841 4840,3890 显示屏1.3
TX1: EX1.4 LQ-TC1.65 | length 319.5
  Top Layer w10: EX1.4 3219.52,3872.52 3219.52,3660.48 LQ-TC1.65
TX3: EX1.8 LQ-TC1.104 | length 1751.2
  Bottom Layer w10: LQ-TC1.104 1915.26,3265.26 1915.26,3745.26 1980,3810 2957,3810 EX1.8
VCC12V: BAT1.2 开关1.1 | length 1043.9
  Top Layer w50: BAT1.2@4324.66,1850 BAT1.2 4357.51,1850 4442.51,1765 4445,1765 4471.43,1738.57 5152.83,1738.57 5245,1830.75 开关1.1
pads on no net: LQ-TC1.1 LQ-TC1.2 LQ-TC1.3 LQ-TC1.4 LQ-TC1.6 LQ-TC1.8 LQ-TC1.13 LQ-TC1.15 LQ-TC1.16 LQ-TC1.18 LQ-TC1.23 LQ-TC1.25 LQ-TC1.26 LQ-TC1.27 LQ-TC1.33 LQ-TC1.34 LQ-TC1.36 LQ-TC1.37 LQ-TC1.38 LQ-TC1.39 LQ-TC1.41 LQ-TC1.42 LQ-TC1.44 LQ-TC1.45 LQ-TC1.47 LQ-TC1.48 LQ-TC1.49 LQ-TC1.50 LQ-TC1.51 LQ-TC1.54 LQ-TC1.62 LQ-TC1.64 LQ-TC1.66 LQ-TC1.70 LQ-TC1.71 LQ-TC1.72 LQ-TC1.73 LQ-TC1.75 LQ-TC1.78 LQ-TC1.79 LQ-TC1.80 LQ-TC1.81 LQ-TC1.82 LQ-TC1.83 LQ-TC1.84 LQ-TC1.85 LQ-TC1.86 LQ-TC1.87 LQ-TC1.88 LQ-TC1.89 LQ-TC1.90 LQ-TC1.91 LQ-TC1.92 LQ-TC1.93 LQ-TC1.94 LQ-TC1.95 LQ-TC1.96 LQ-TC1.97 LQ-TC1.98 LQ-TC1.100 LQ-TC1.101 LQ-TC1.102 LQ-TC1.103 LQ-TC1.105 LQ-TC1.106 LQ-TC1.107 LQ-TC1.108 LQ-TC1.109 LQ-TC1.110 LQ-TC1.111 LQ-TC1.112 LQ-TC1.113 LQ-TC1.114 LQ-TC1.115 LQ-TC1.116 LQ-TC1.117 LQ-TC1.118 LQ-TC1.119 LQ-TC1.120 LQ-TC1.121 LQ-TC1.122 LQ-TC1.123 LQ-TC1.124 LQ-TC1.125 LQ-TC1.126 LQ-TC1.127 U1.0 U2.4 VR1.1 编码器1.5 编码器1.6 舵机1.4

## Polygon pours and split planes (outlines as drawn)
GND on Bottom Layer "GND_L02_P000" (solid, remove dead copper, pour order 0): 1790,1830 ccw(c1943.01,1842.73) 1925.4,1690.2 1925.4,1689.8 5775,1689.8 5775,1690 ccw(c5762.27,1843.01) 5914.8,1825.4 5915,1825.4 5915,4030 ccw(c5761.99,4017.27) 5779.6,4169.8 5779.6,4170 1930,4170 ccw(c1942.73,4016.99) 1790.2,4034.6 1790,4034.6
GND on Top Layer "GND_L01_P001" (solid, remove dead copper, pour order 1): 1790,1830 ccw(c1943.01,1842.73) 1925.4,1690.2 1925.4,1689.8 5775,1689.8 5775,1690 ccw(c5762.27,1843.01) 5914.8,1825.4 5915,1825.4 5915,4030 ccw(c5761.99,4017.27) 5779.6,4169.8 5779.6,4170 1930,4170 ccw(c1942.73,4016.99) 1790.2,4034.6 1790,4034.6

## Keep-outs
Keep-Out Layer:
  lines w11.81: 1790,4034.6 1790,1830 ccw(c1943.01,1842.73) 1925.4,1690.2 ; 1790.2,4034.6 cw(c1942.73,4016.99) 1930,4170 5779.6,4170 ; 1925.4,1689.8 5775,1689.8 ; 5775,1690 ccw(c5762.27,1843.01) 5914.8,1825.4 ; 5779.6,4169.8 cw(c5761.99,4017.27) 5915,4030 5915,1825.4

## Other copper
Top Layer:
  text "合肥经济学院" at 2140.09,4004.29 h98.43
  text "凌队 2021.7.8" at 2235,3907.14 h78.74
